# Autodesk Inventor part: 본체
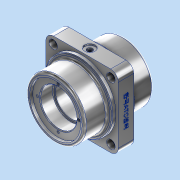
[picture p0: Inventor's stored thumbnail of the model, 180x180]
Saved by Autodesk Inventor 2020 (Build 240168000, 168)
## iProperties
Created: 2023-10
Part Number: 본체
Material: 알루미늄 6061
Document SubType Name: Modeling
Designer: CAD14
Density: 2.7 g/cm^3
Appearance: 알루미늄 - 평지
Mass: 945.786 g
Surface Area: 536.974 cm^2
Volume: 350.291 cm^3
Author: CAD14
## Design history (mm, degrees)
sketch "스케치1"
  geometry: L1 (-45, 0)-(45, 0); L2 (-45, 38)-(45, 38); L3 (-45, 38)-(-45, 33); L4 (-45, 33)-(-41, 33); L5 (-41, 33)-(-41, 23.5); L6 (-41, 23.5)-(-24, 23.5); L7 (-24, 23.5)-(-24, 20.5); L8 (-24, 20.5)-(24, 20.5); L9 (24, 20.5)-(24, 23.5); L10 (24, 23.5)-(41, 23.5); L11 (41, 23.5)-(41, 33); L12 (41, 33)-(45, 33); L13 (45, 33)-(45, 38); 2 further points
  constraints: 26 end point, 10 perpendicular, 3 equal length, 2 horizontal, 2 vertical alignment, 1 coincident, 1 midpoint, 1 vertical
  dimensions: "d0" = 90 distance of L1.start L1.end; "d2" = 41 diameter of L8 L1; "d3" = 47 diameter of L6 L1; "d4" = 66 diameter of L4 L1; "d5" = 76 diameter of L2 L1; "d6" = 4 distance between parallel lines of L5 L3; "d7" = 17 distance between parallel lines of L7 L5; "d8" = 17 distance between parallel lines of L9 L11
revolve "회전1" sketch "스케치1" stored, may be unused: angle "d9" = 90 deg
sketch "스케치2"
  geometry: L1 (47, -47)-(-47, -47); L2 (-47, -47)-(-47, 47); L3 (-47, 47)-(47, 47); L4 (47, 47)-(47, -47); L5 (47, -47)-(-47, 47); L6 (-47, -47)-(47, 47); 1 further point
  constraints: 12 end point, 2 midpoint, 2 parallel, 1 horizontal, 1 perpendicular
  dimensions: "d10" = 94 distance of L2.end L3.end; "d11" = 94 distance of L1.end L2.end
extrude "돌출1" join sketch "스케치2" stored distance "d12" = 20; taper "d13" = 0 deg
sketch "스케치3"
  geometry: C1 r 44 at (0, 0); 1 further point
  constraints: 1 centre point, 1 coincident
  dimensions: "d14" = 88 diameter of C1
extrude "돌출2" join sketch "스케치3" distance "d15" = 5; taper "d16" = 0 deg
sketch "스케치4"
  geometry: C1 r 44 at (0, 0); 1 further point
  constraints: 1 centre point, 1 coincident
  dimensions: "d17" = 88 diameter of C1
extrude "돌출3" join sketch "스케치4" distance "d18" = 5; taper "d19" = 0 deg
sketch "스케치5"
  geometry: 1 further point
fillet "모깎기1" dims "d21" = 10
sketch "스케치8"
  geometry: L1 (0, 0)-(0, 27); 1 further point
  constraints: 2 end point, 1 coincident, 1 vertical
  dimensions: "d23" = 27 distance of L1.start L1.end
hole "구멍1" sketch "스케치8" at (0, 27) diameter "d24" = 3.242; stored, may be unused: countersink angle "d28" = 90 deg, drill point angle "d30" = 118 deg; dims "d25" = 8, "d26" = 4, "d27" = 2, "d29" = 10
sketch "스케치9"
  geometry: C1 r 7 at (37, 10); 2 further points
  constraints: 2 coincident, 1 centre point
  dimensions: "d34" = 14 diameter of C1
extrude "돌출4" cut sketch "스케치9" distance "d35" = 2; taper "d36" = 0 deg
sketch "스케치10"
  geometry: C1 r 3.5 at (0, 0); 1 further point
  constraints: 1 centre point, 1 coincident
  dimensions: "d37" = 7 diameter of C1
extrude "돌출5" cut sketch "스케치10" distance "d38" = 2; taper "d39" = 0 deg
sketch "스케치11"
  geometry: C1 r 3.5 at (0, 0) reference; 2 further points
  constraints: 1 coincident
hole "구멍2" sketch "스케치11" at (0, 0) diameter "d40" = 5.1881; stored, may be unused: countersink angle "d44" = 90 deg, drill point angle "d46" = 118 deg; dims "d41" = 12, "d42" = 4, "d43" = 2, "d45" = 16
sketch "스케치12"
  geometry: C1 r 20.5 at (0, 0) reference; C2 r 20.5 at (0, 0); 1 further point
  constraints: 1 centre point, 1 coincident, 1 concentric
extrude "돌출6" cut sketch "스케치12" distance "d47" = 90; taper "d48" = 0 deg
sketch "스케치13"
  geometry: L1 (0, 0)-(63.902, 0); C1 r 3.3 at (37.477, 37.477); 1 further point
  constraints: 2 end point, 1 centre point, 1 coincident, 1 horizontal
  dimensions: "d52" = 6.6 diameter of C1
extrude "돌출7" cut sketch "스케치13" stored distance "d54" = 20; taper "d55" = 0 deg
sketch "스케치14"
  geometry: C1 r 3.3 at (-37.477, 37.477) reference; C2 r 5.5 at (-37.477, 37.477); 1 further point
  constraints: 1 centre point, 1 coincident
  dimensions: "d56" = 11 diameter of C2
extrude "돌출8" cut sketch "스케치14" distance "d57" = 7; taper "d58" = 0 deg
sketch "스케치15"
  geometry: L1 (0, 0)-(-74, 0) reference; 2 further points
  constraints: 1 coincident, 1 other
  dimensions: "d59" = 10 distance from line of L1 point (-37, 10)
feature "엠보싱1" sketch "스케치15" dims "d10" = 94, "d11" = 94, "d60" = 0.5, "d61" = 0
fillet "모깎기2" dims "d62" = 3
chamfer "모따기1" distance "d63" = 1; stored, may be unused: second distance "d64" = 2, angle "d65" = 45 deg
fillet "모깎기3" dims "d66" = 3
chamfer "모따기2" distance "d67" = 1; stored, may be unused: second distance "d68" = 2, angle "d69" = 45 deg
fillet "모깎기4" dims "d70" = 1
sketch "스케치16"
  geometry: C1 r 3.3 at (37.477, -37.477) reference; C2 r 3.3 at (37.477, 37.477) reference; C3 r 3.3 at (-37.477, 37.477) reference; C4 r 5.5 at (37.477, -37.477) reference; C5 r 5.5 at (37.477, -37.477); C6 r 5.5 at (37.477, 37.477) reference; C7 r 5.5 at (37.477, 37.477); C8 r 5.5 at (-37.477, 37.477) reference; C9 r 5.5 at (-37.477, 37.477); 1 further point
  constraints: 3 centre point, 3 coincident
  dimensions: "d71" = 11 diameter of C5; "d72" = 11 diameter of C7; "d73" = 11 diameter of C9
extrude "돌출9" cut sketch "스케치16" distance "d74" = 7; taper "d75" = 0 deg
node "솔리드1"
pattern_circular "원형 패턴1" dims angle "d32" = 360 deg
mirror "미러1"
mirror "미러2"
mirror "미러3"
mirror "미러4"
feature "A9D066F2-1C7D-4E18-AEED-F7BC21143FA4" dims "d24" = 3.242, "d25" = 8, "d26" = 4, "d27" = 2, "d28" = 90 deg, "d29" = 10, "d30" = 118 deg
